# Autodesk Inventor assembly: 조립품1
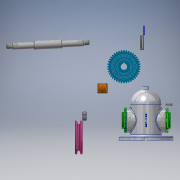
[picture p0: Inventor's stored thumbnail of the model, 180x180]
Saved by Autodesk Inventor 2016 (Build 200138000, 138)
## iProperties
Created: 2019-11
Part Number: 조립품1
Material: 일반
Document SubType Name: Assembly
Designer: 605-04
Author: 605-04
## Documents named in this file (14)
- C:\Users\605-04\Desktop\491104V1001\조립품1.iam
- C:\Users\605-04\Desktop\491104V1001\본체.ipt
- C:\Users\605-04\Desktop\491104V1001\V-벨트풀리.ipt
- V-벨트풀리.ipt
- C:\Users\605-04\Desktop\491104V1001\너트 M12x1.25.ipt
- C:\Users\605-04\Desktop\491104V1001\베어링 6203.ipt
- C:\Users\605-04\Desktop\491104V1001\볼트 M4.ipt
- C:\Users\605-04\Desktop\491104V1001\부시.ipt
- C:\Users\605-04\Desktop\491104V1001\스퍼기어.ipt
- C:\Users\605-04\Desktop\491104V1001\오일 실 26 38 8.ipt
- C:\Users\605-04\Desktop\491104V1001\와셔 12x24.ipt
- C:\Users\605-04\Desktop\491104V1001\축.ipt
- C:\Users\605-04\Desktop\491104V1001\커버.ipt
- C:\Users\605-04\Desktop\491104V1001\키 5x5x12.ipt
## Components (1 placed, 1 different names)
1. V-벨트풀리:1
## Named parameters: d3_d2 = 0
